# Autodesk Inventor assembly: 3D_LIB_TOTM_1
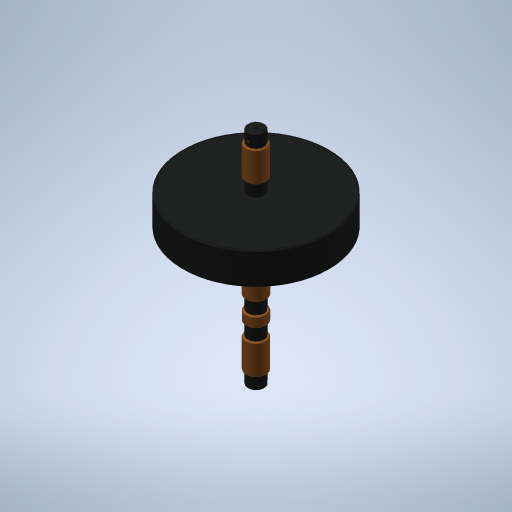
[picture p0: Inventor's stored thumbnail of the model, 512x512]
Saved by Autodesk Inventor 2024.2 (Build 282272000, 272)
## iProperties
Manager: Filip
Company: DARK
Created: 2023-05
Part Number: 3D_LIB_TOTM_1
Document SubType Name: Assembly
Designer: Manuel
Project: 442 - TOTM
Description: TOTM Small - Suspension
Author: Manuel
Revision Number: v0
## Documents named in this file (15)
- C:\Users\Stage\Desktop\Stage Karsten\armatures\TOTM - Wall\442_KARSTEN\3D_LIB_TOTM_1.iam
- C:\Users\Stage\Desktop\Stage Barend Nijs\3D\totm\442 - TOTM\442 - TOTM\TOTM - Small\442-081.ipt
- C:\Users\Stage\Desktop\Stage Barend Nijs\3D\totm\442 - TOTM\442 - TOTM\TOTM - Small\442-082.ipt
- C:\Users\Stage\Desktop\Stage Barend Nijs\3D\totm\442 - TOTM\442 - TOTM\TOTM - Small\442-083.ipt
- C:\Users\Stage\Desktop\Stage Barend Nijs\3D\totm\442 - TOTM\442 - TOTM\TOTM - Small\442-085.ipt
- C:\Users\Stage\Desktop\Stage Barend Nijs\3D\totm\442 - TOTM\442 - TOTM\TOTM - Small\442-084.ipt
- C:\Users\Stage\Desktop\Stage Barend Nijs\3D\totm\442 - TOTM\442 - TOTM\TOTM - Small\442-086.ipt
- C:\Users\Stage\Desktop\Stage Barend Nijs\3D\totm\442 - TOTM\442 - TOTM\TOTM - Small\442-087.ipt
- C:\Users\Stage\Desktop\Stage Barend Nijs\3D\totm\442 - TOTM\442 - TOTM\TOTM - Small\442-088.ipt
- C:\Users\Stage\Desktop\Stage Barend Nijs\3D\totm\442 - TOTM\442 - TOTM\TOTM - Small\442-090.ipt
- C:\Users\Stage\Desktop\Stage Barend Nijs\3D\totm\442 - TOTM\442 - TOTM\TOTM - Small\442-091.ipt
- C:\Users\Stage\Desktop\Stage Barend Nijs\3D\totm\442 - TOTM\442 - TOTM\TOTM - Small\442-092.ipt
- C:\Users\Stage\Desktop\Stage Barend Nijs\3D\totm\442 - TOTM\442 - TOTM\TOTM - Medium (Old)\Draadstang M10x1 L85.ipt
- C:\Users\Stage\Desktop\Stage Barend Nijs\3D\totm\442 - TOTM\442 - TOTM\Draadstang M10x1 L180.ipt
- C:\Users\Stage\Desktop\Stage Barend Nijs\3D\totm\442 - TOTM\442 - TOTM\TOTM - Small\160LED-IP20-2700.ipt
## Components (29 placed, 14 different names)
1. 442-081:1
2. 442-082:1 — Mate:1, Mate:2, Mate:27, Angle:2
3. 442-083:1 — Mate:7, Mate:8, Mate:9, Mate:10
4. 442-085:1 — Mate:3, Mate:4, Mate:5, Mate:6
5. 442-084:1 — Mate:13, Mate:14, Mate:19, Mate:20
6. 442-084:2 — Mate:11, Mate:12, Mate:21, Mate:22
7. 442-086:1 — Mate:13, Mate:14, Mate:15, Mate:16
8. 442-086:2 — Mate:9, Mate:10, Mate:11, Mate:12
9. 442-086:3 — Mate:5, Mate:6, Mate:7, Mate:8
10. 442-086:4 — Mate:3, Mate:4, Mate:17, Mate:18, Mate:28
11. 442-087:1 — Mate:19, Mate:20
12. 442-088:1 — Mate:21, Mate:22
13. 442-090:1 — Mate:23, Mate:24
14. 442-091:1 — Mate:25, Mate:26
15. 442-092:1 — Mate:27, Mate:28, Mate:29, Mate:30, Mate:31, Mate:32
16. Draadstang M10x1 L85:1 — Mate:31, Mate:32
17. Draadstang M10x1 L180:1 — Mate:29, Mate:30
18. 160LED-IP20-2700:1 — Mate:35, Mate:36, Flush:1
19. 160LED-IP20-2700:2
20. 160LED-IP20-2700:3
21. 160LED-IP20-2700:4
22. 160LED-IP20-2700:5
23. 160LED-IP20-2700:6
24. 160LED-IP20-2700:7
25. 160LED-IP20-2700:8
26. 160LED-IP20-2700:9
27. 160LED-IP20-2700:10
28. 160LED-IP20-2700:11
29. 160LED-IP20-2700:12
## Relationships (36: Mate 34, Flush 1, Angle 1)
- Mate:1: 442-082:1
- Mate:2: 442-082:1
- Mate:3: 442-085:1 ↔ 442-086:4
- Mate:4: 442-085:1 ↔ 442-086:4
- Mate:5: 442-085:1 ↔ 442-086:3
- Mate:6: 442-085:1 ↔ 442-086:3
- Mate:7: 442-083:1 ↔ 442-086:3
- Mate:8: 442-083:1 ↔ 442-086:3
- Mate:9: 442-083:1 ↔ 442-086:2
- Mate:10: 442-083:1 ↔ 442-086:2
- Mate:11: 442-084:2 ↔ 442-086:2
- Mate:12: 442-084:2 ↔ 442-086:2
- Mate:13: 442-084:1 ↔ 442-086:1
- Mate:14: 442-084:1 ↔ 442-086:1
- Mate:15: 442-086:1
- Mate:16: 442-086:1
- Mate:17: 442-086:4
- Mate:18: 442-086:4
- Mate:19: 442-084:1 ↔ 442-087:1
- Mate:20: 442-084:1 ↔ 442-087:1
- Mate:21: 442-084:2 ↔ 442-088:1
- Mate:22: 442-084:2 ↔ 442-088:1
- Mate:23: 442-090:1
- Mate:24: 442-090:1
- Mate:25: 442-091:1
- Mate:26: 442-091:1
- Mate:27: 442-082:1 ↔ 442-092:1
- Mate:28: 442-086:4 ↔ 442-092:1
- Mate:29: 442-092:1 ↔ Draadstang M10x1 L180:1
- Mate:30: 442-092:1 ↔ Draadstang M10x1 L180:1
- Mate:31: 442-092:1 ↔ Draadstang M10x1 L85:1
- Mate:32: 442-092:1 ↔ Draadstang M10x1 L85:1
- Mate:35: 160LED-IP20-2700:1
- Mate:36: 160LED-IP20-2700:1
- Flush:1: 160LED-IP20-2700:1
- Angle:2: 442-082:1
